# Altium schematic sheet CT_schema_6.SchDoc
size 359 x 243 mm
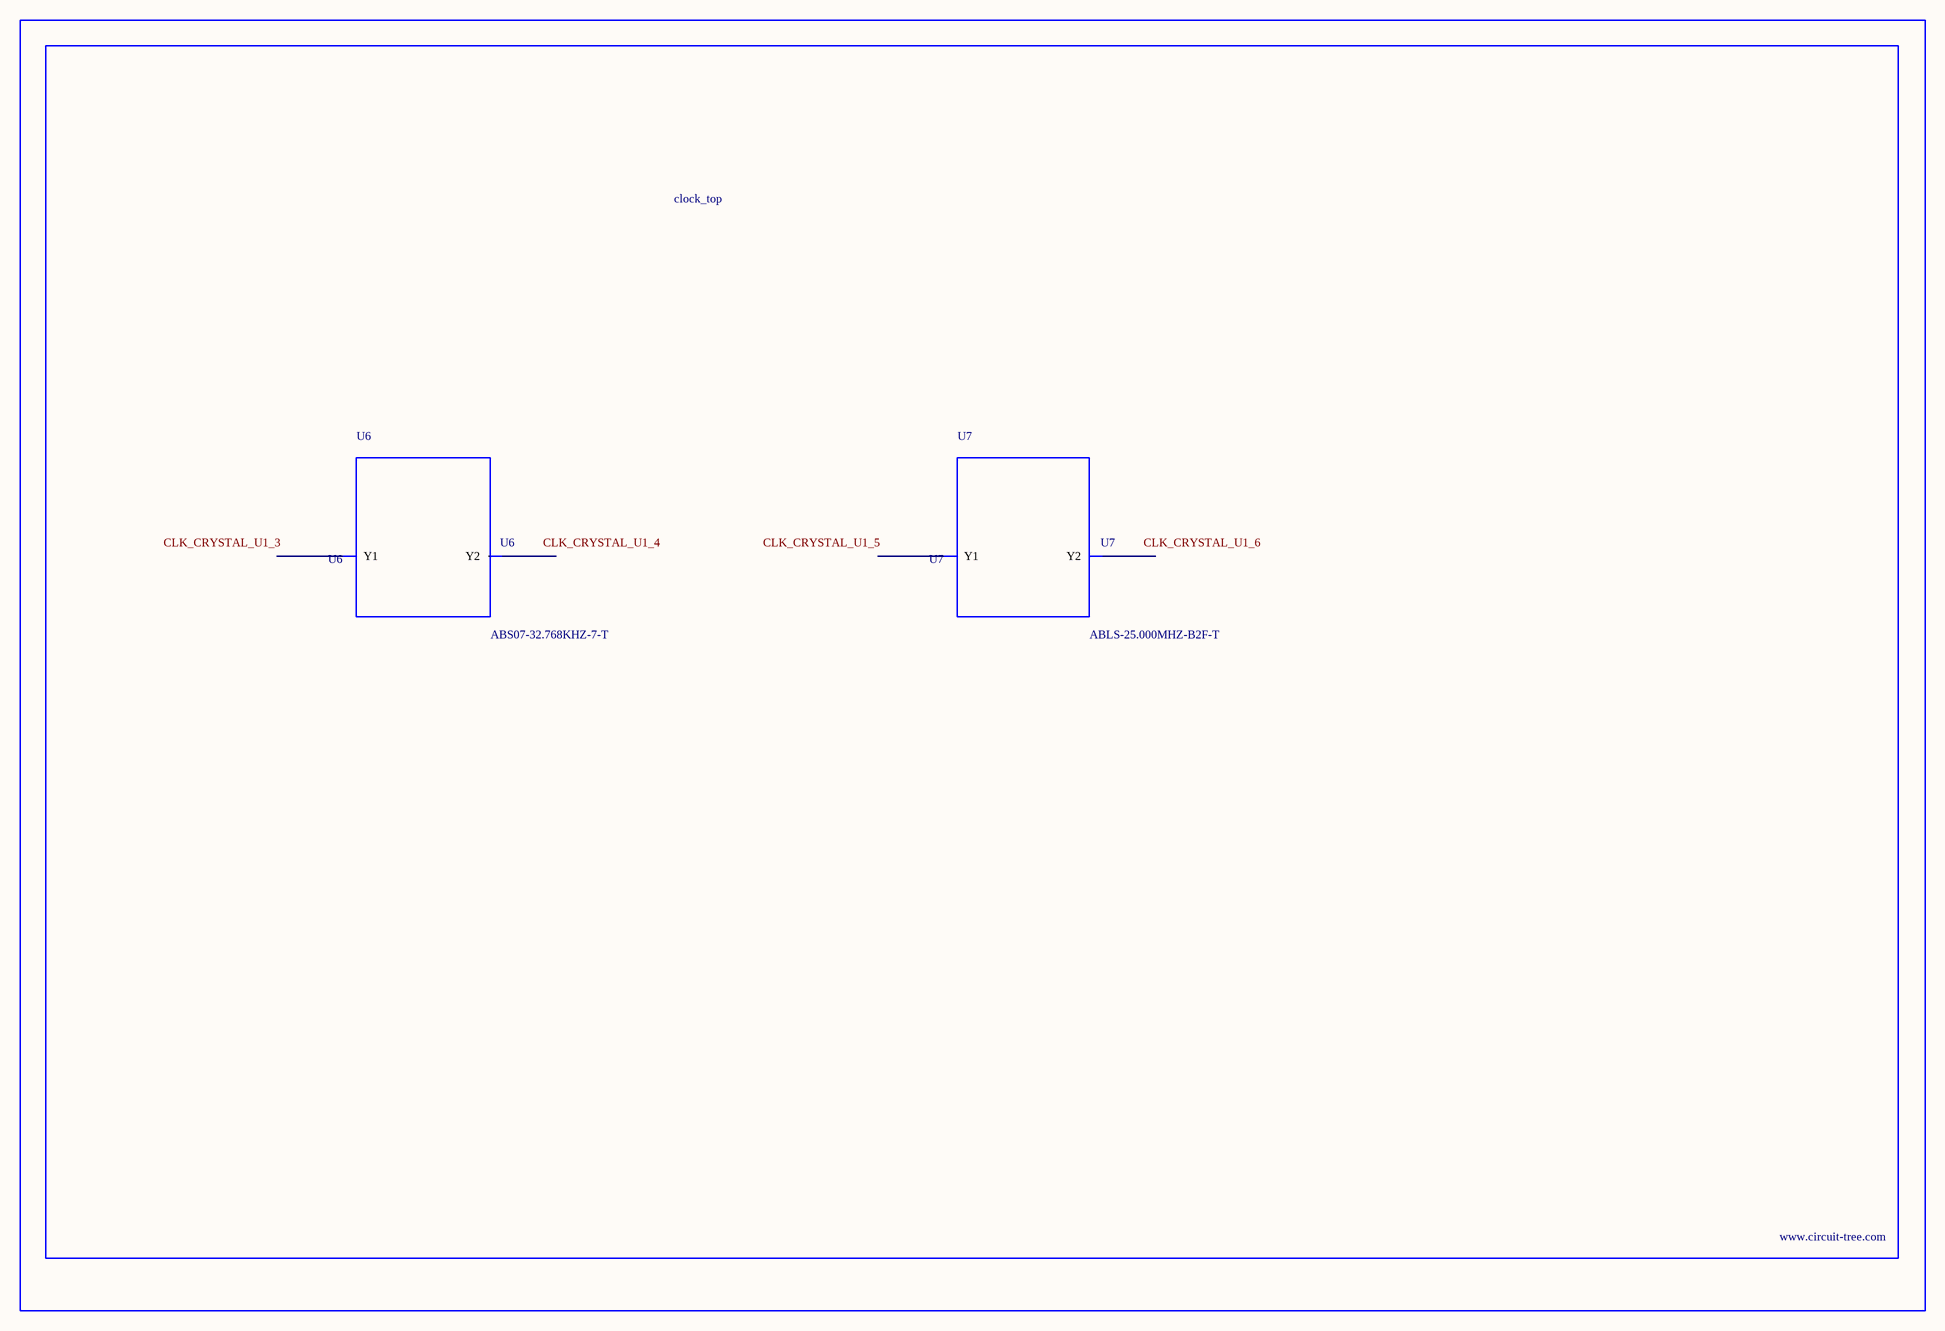
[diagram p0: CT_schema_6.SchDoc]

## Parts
BORDER5  (no value)
U6  ABS07-32.768KHZ-7-T  [ABS07-32.768KHZ-7-T]
U7  ABLS-25.000MHZ-B2F-T  [ABLS-25.000MHZ-B2F-T]

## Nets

Not connected (* = marked no-connect by the designer): U6 1(Y1) 2(Y2); U7 1(Y1) 2(Y2)

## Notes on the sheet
- Labels drawn without touching a wire or pin: CLK_CRYSTAL_U1_3, CLK_CRYSTAL_U1_4, CLK_CRYSTAL_U1_5, CLK_CRYSTAL_U1_6

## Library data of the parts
BORDER5 = BORDER_PAGE5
